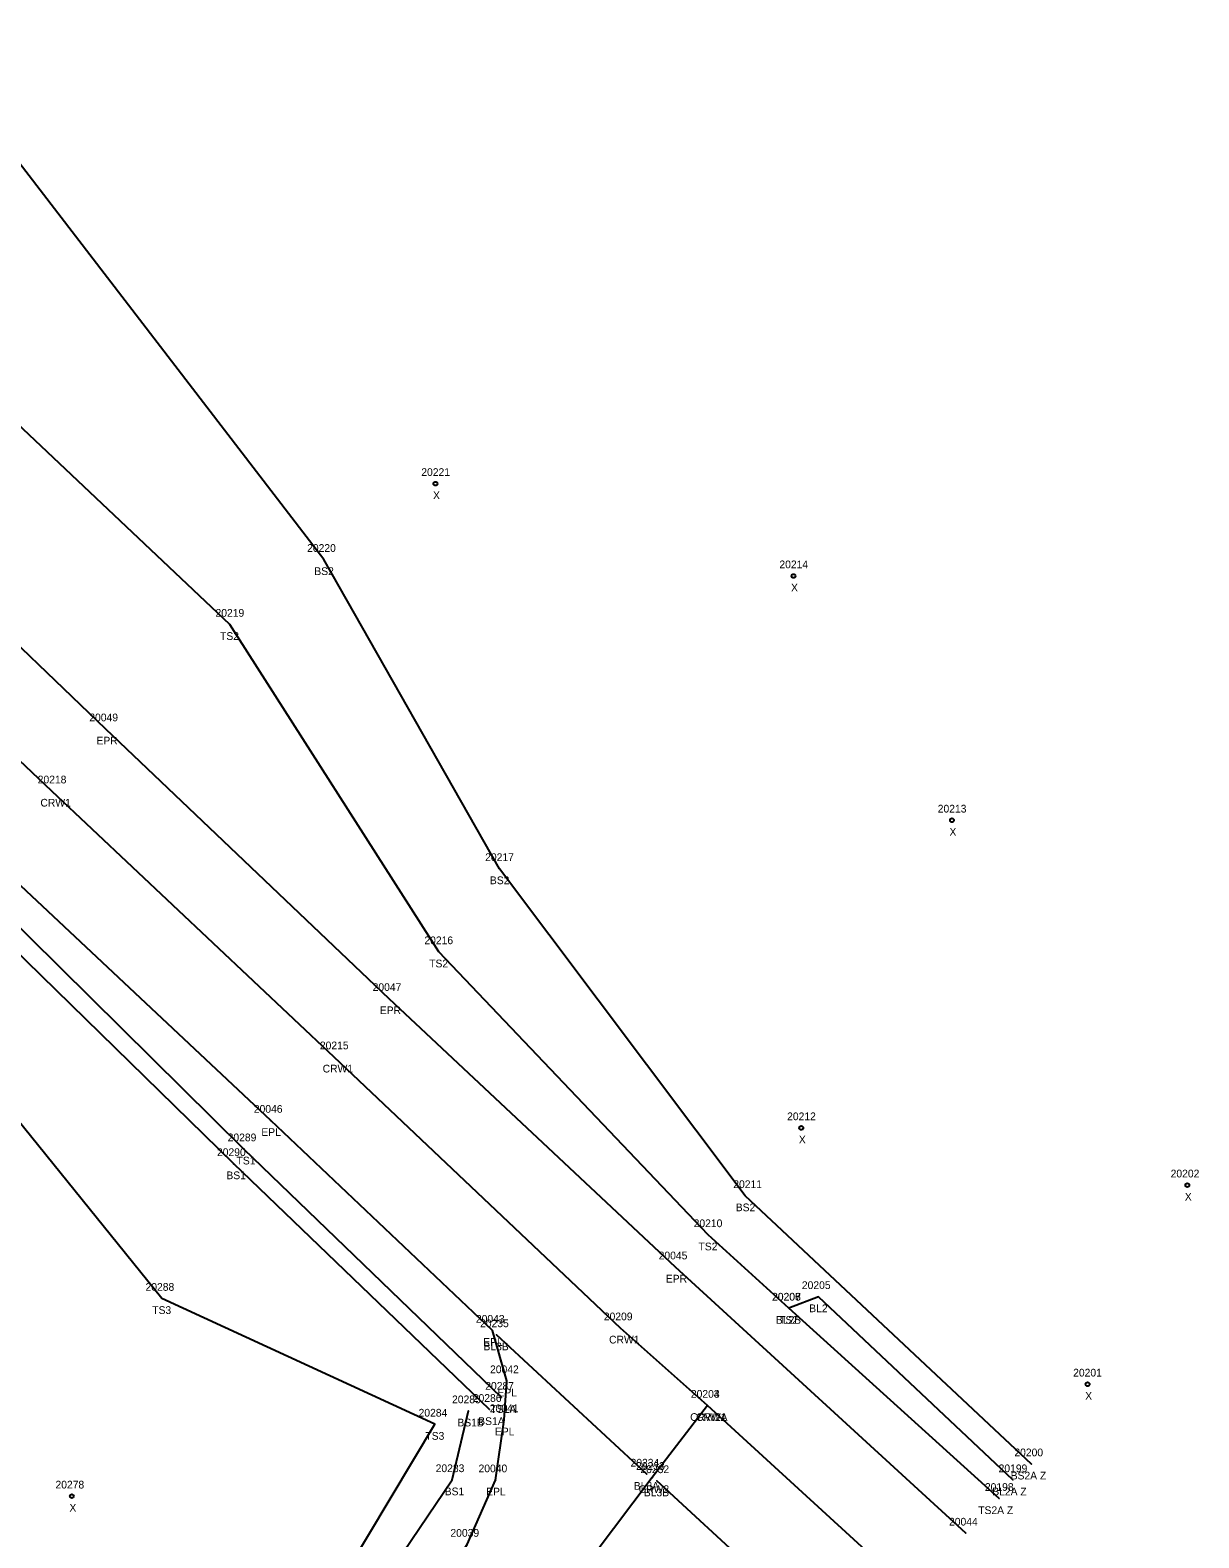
# Model space of a CAD drawing. Extents: x 1813127 to 1814107, y 1178171 to 1179078.
# Drawn here: x 1813955.3 to 1814106.6, y 1178426.8 to 1178622 of the extents above; entities that cross this region are included whole.
import ezdxf

# ---------------------------------------------------------------- set-up
doc = ezdxf.new("R2010")
doc.units = 0
for name, color, linetype in [('RD_DTM_BkLn1', 7, 'Continuous'), ('RD_DTM_BkLn2', 7, 'Continuous'), ('RD_EX_Road', 7, 'Continuous'), ('RD_EX_Road_txCode', 7, 'Continuous'), ('RD_SMD_Locator', 7, 'Continuous'), ('RD_SMD_Misc', 7, 'Continuous')]:
    doc.layers.add(name, color=color, linetype=linetype)

msp = doc.modelspace()

# ---------------------------------------------------------------- linework, layer by layer
at = {"layer": 'RD_DTM_BkLn1'}
for p, q in [((1814035.18, 1178435.04), (1814015.7, 1178453.09)), ((1814052.79, 1178419.16), (1814036.46, 1178434.19))]:
    msp.add_line(p, q, dxfattribs=at)
for points in [[(1814069.63, 1178419.56), (1814043.03, 1178443.95), (1814031.76, 1178453.98), (1813994.68, 1178489.07), (1813958.14, 1178523.5), (1813920.87, 1178558.86), (1813884.46, 1178593.47), (1813847.15, 1178628.98), (1813831.28, 1178643.33), (1813810.03, 1178662.5), (1813772.7, 1178693.86)], [(1814082.54, 1178434.31), (1814057.4, 1178458.03), (1814053.55, 1178456.53)], [(1814043.03, 1178443.95), (1814035.88, 1178434.61), (1814028.35, 1178424.67), (1814012.24, 1178403.85), (1813982.68, 1178367.11), (1813951.35, 1178327.47), (1813918.15, 1178289.3), (1813882.49, 1178251.63), (1813838.5, 1178201.85)]]:
    msp.add_lwpolyline(points, dxfattribs=at)
at = {"layer": 'RD_DTM_BkLn2'}
for points in [[(1814080.77, 1178431.89), (1814053.55, 1178456.53), (1814053.55, 1178456.53), (1814043.11, 1178466.04), (1814008.23, 1178502.68), (1813981.17, 1178545.08), (1813940.17, 1178583.78), (1813898.27, 1178611.44), (1813860.48, 1178642.94), (1813824.26, 1178675.11), (1813790.56, 1178704.96), (1813785.53, 1178702.33), (1813780.61, 1178703.45)], [(1814084.95, 1178436.37), (1814047.91, 1178471.1), (1814016.08, 1178513.45), (1813993.35, 1178553.48), (1813952.47, 1178606.71), (1813860.87, 1178652.01), (1813829.57, 1178687.07), (1813824.98, 1178702.29)], [(1814016.37, 1178444.99), (1813983.01, 1178477.16), (1813947.31, 1178512.42), (1813910.48, 1178547.16), (1813873.41, 1178582.28), (1813839.61, 1178613.47), (1813832.17, 1178619.82), (1813823.6, 1178617.43)], [(1814014.78, 1178443.42), (1813981.68, 1178475.25), (1813945.25, 1178510.83), (1813909.11, 1178545.75), (1813871.28, 1178580.16), (1813838.14, 1178611.58), (1813831.82, 1178617.25), (1813823.34, 1178615.53), (1813787.27, 1178592.92)], [(1813893.16, 1178338.84), (1813921.32, 1178364.43), (1813929.94, 1178352.15), (1813936.66, 1178353.94), (1813964.13, 1178381.53), (1813993.38, 1178417.59), (1814007.74, 1178441.51), (1813972.38, 1178457.8), (1813931.97, 1178507.78), (1813904.27, 1178536.29), (1813860.78, 1178571.07), (1813835.97, 1178602.37), (1813828.98, 1178599.83), (1813813.84, 1178586.1), (1813811.52, 1178575.86), (1813773.95, 1178566.06)], [(1813975.63, 1178383.15), (1813996.19, 1178413.93), (1814009.95, 1178434.32), (1814012.07, 1178443.24)]]:
    msp.add_lwpolyline(points, dxfattribs=at)
at = {"layer": 'RD_EX_Road'}
for points in [[(1814076.45, 1178427.4), (1814038.86, 1178461.87), (1814001.83, 1178496.62), (1813965.15, 1178531.54), (1813928.08, 1178567.1), (1813892.01, 1178601.23), (1813854.54, 1178636.51), (1813817.44, 1178670.03), (1813779.87, 1178701.64)], [(1813829.87, 1178208.6), (1813830.81, 1178209.56), (1813845.51, 1178227.94), (1813874.69, 1178258.74), (1813910.02, 1178295.38), (1813943.63, 1178333.84), (1813974.31, 1178373.09), (1814001.91, 1178410.56), (1814011.9, 1178425.95), (1814015.58, 1178434.3), (1814016.71, 1178442.08), (1814017.03, 1178447.13), (1814015.19, 1178453.67), (1813986.47, 1178480.85), (1813949.15, 1178515.86), (1813911.94, 1178551.77), (1813875.67, 1178586.1), (1813838.32, 1178620.7), (1813831.51, 1178622), (1813823.35, 1178621.08), (1813815.99, 1178618.51), (1813795.14, 1178605.39)]]:
    msp.add_lwpolyline(points, dxfattribs=at)
at = {"layer": 'RD_SMD_Locator'}
for centre, radius in [((1814007.8, 1178563.31), 0.25), ((1813993.35, 1178553.48), 0.001), ((1814054.16, 1178551.36), 0.25), ((1813981.17, 1178545.08), 0.001), ((1813965.15, 1178531.54), 0.001), ((1813958.14, 1178523.5), 0.001), ((1814074.67, 1178519.73), 0.25), ((1814016.08, 1178513.45), 0.001), ((1814008.23, 1178502.68), 0.001), ((1814001.83, 1178496.62), 0.001), ((1813994.68, 1178489.07), 0.001), ((1813986.47, 1178480.85), 0.001), ((1814055.16, 1178479.89), 0.25), ((1813983.01, 1178477.16), 0.001), ((1813981.68, 1178475.25), 0.001), ((1814105.14, 1178472.48), 0.25), ((1814047.91, 1178471.1), 0.001), ((1814043.11, 1178466.04), 0.001), ((1814038.86, 1178461.87), 0.001), ((1813972.38, 1178457.8), 0.001), ((1814053.55, 1178456.53), 0.001), ((1814053.55, 1178456.53), 0.001), ((1814053.55, 1178456.53), 0.001), ((1814057.4, 1178458.03), 0.001), ((1814015.19, 1178453.67), 0.001), ((1814015.7, 1178453.09), 0.001), ((1814031.76, 1178453.98), 0.001), ((1814017.03, 1178447.13), 0.001), ((1814092.23, 1178446.7), 0.25), ((1814016.37, 1178444.99), 0.001), ((1814012.07, 1178443.24), 0.001), ((1814014.78, 1178443.42), 0.001), ((1814043.03, 1178443.95), 0.001), ((1814043.03, 1178443.95), 0.001), ((1814007.74, 1178441.51), 0.001), ((1814016.71, 1178442.08), 0.001), ((1814084.95, 1178436.37), 0.001), ((1814009.95, 1178434.32), 0.001), ((1814015.58, 1178434.3), 0.001), ((1814035.18, 1178435.04), 0.001), ((1814035.88, 1178434.61), 0.001), ((1814036.46, 1178434.19), 0.001), ((1814082.54, 1178434.31), 0.001), ((1813960.73, 1178432.2), 0.25), ((1814080.77, 1178431.89), 0.001), ((1814076.45, 1178427.4), 0.001)]:
    msp.add_circle(centre, radius, dxfattribs=at)

# ---------------------------------------------------------------- texts
at = {"layer": 'RD_EX_Road_txCode'}
for s, p in [('20049', (1813962.99, 1178532.54)), ('EPR', (1813963.92, 1178529.54)), ('20047', (1813999.67, 1178497.62)), ('EPR', (1814000.6, 1178494.62)), ('20046', (1813984.29, 1178481.85)), ('EPL', (1813985.26, 1178478.85)), ('20045', (1814036.7, 1178462.87)), ('EPR', (1814037.63, 1178459.87)), ('20043', (1814013.04, 1178454.67)), ('EPL', (1814013.99, 1178451.67)), ('20042', (1814014.87, 1178448.13)), ('EPL', (1814015.83, 1178445.13)), ('20041', (1814014.83, 1178443.08)), ('EPL', (1814015.5, 1178440.08)), ('20040', (1814013.38, 1178435.3)), ('EPL', (1814014.37, 1178432.3)), ('20044', (1814074.29, 1178428.4)), ('20039', (1814009.74, 1178426.95))]:
    msp.add_text(s, height=1, dxfattribs=at).set_placement(p)
at = {"layer": 'RD_SMD_Misc'}
for s, p in [('20221', (1814005.97, 1178564.31)), ('X', (1814007.49, 1178561.31)), ('20220', (1813991.19, 1178554.48)), ('BS2', (1813992.12, 1178551.48)), ('20214', (1814052.33, 1178552.36)), ('X', (1814053.84, 1178549.36)), ('20219', (1813979.33, 1178546.08)), ('TS2', (1813979.92, 1178543.08)), ('20218', (1813956.31, 1178524.5)), ('CRW1', (1813956.66, 1178521.5)), ('20213', (1814072.83, 1178520.73)), ('X', (1814074.35, 1178517.73)), ('20217', (1814014.24, 1178514.45)), ('BS2', (1814014.85, 1178511.45)), ('20216', (1814006.37, 1178503.68)), ('TS2', (1814006.99, 1178500.68)), ('20215', (1813992.84, 1178490.07)), ('CRW1', (1813993.2, 1178487.07)), ('20212', (1814053.33, 1178480.89)), ('20289', (1813980.9, 1178478.16)), ('X', (1814054.85, 1178477.89)), ('20290', (1813979.52, 1178476.25)), ('TS1', (1813982.05, 1178475.16)), ('BS1', (1813980.74, 1178473.25)), ('20202', (1814102.98, 1178473.48)), ('20211', (1814046.36, 1178472.1)), ('X', (1814104.82, 1178470.48)), ('BS2', (1814046.68, 1178469.1)), ('20210', (1814041.23, 1178467.04)), ('TS2', (1814041.86, 1178464.04)), ('20288', (1813970.27, 1178458.8)), ('20206', (1814051.37, 1178457.53)), ('20207', (1814051.39, 1178457.53)), ('20208', (1814051.39, 1178457.53)), ('20205', (1814055.24, 1178459.03)), ('TS3', (1813971.14, 1178455.8)), ('BL2', (1814056.19, 1178456.03)), ('20235', (1814013.58, 1178454.09)), ('20209', (1814029.6, 1178454.98)), ('BL2B', (1814051.87, 1178454.53)), ('TS2', (1814052.3, 1178454.53)), ('TS2', (1814052.3, 1178454.53)), ('CRW1', (1814030.28, 1178451.98)), ('BL3B', (1814014.02, 1178451.09)), ('20201', (1814090.36, 1178447.7)), ('20287', (1814014.25, 1178445.99)), ('20285', (1814009.95, 1178444.24)), ('20286', (1814012.64, 1178444.42)), ('20203', (1814040.87, 1178444.95)), ('20204', (1814040.87, 1178444.95)), ('X', (1814091.92, 1178444.7)), ('20284', (1814005.62, 1178442.51)), ('TS1A', (1814014.92, 1178442.99)), ('CRW2A', (1814040.78, 1178441.95)), ('CRW1', (1814041.55, 1178441.95)), ('BS1B', (1814010.65, 1178441.24)), ('BS1A', (1814013.34, 1178441.42)), ('TS3', (1814006.5, 1178439.51)), ('20234', (1814033.06, 1178436.04)), ('20200', (1814082.75, 1178437.37)), ('20283', (1814007.83, 1178435.32)), ('20233', (1814033.77, 1178435.61)), ('20232', (1814034.34, 1178435.19)), ('20199', (1814080.71, 1178435.31)), ('BS2A Z', (1814082.27, 1178434.37)), ('20278', (1813958.61, 1178433.2)), ('BS1', (1814009, 1178432.32)), ('BL3A', (1814033.48, 1178433.04)), ('CRW2', (1814034.12, 1178432.61)), ('BL3B', (1814034.78, 1178432.19)), ('20198', (1814078.93, 1178432.89)), ('BL2A Z', (1814079.89, 1178432.31)), ('X', (1813960.42, 1178430.2)), ('TS2A Z', (1814078.07, 1178429.89))]:
    msp.add_text(s, height=1, dxfattribs=at).set_placement(p)

doc.saveas('drawing.dxf')
